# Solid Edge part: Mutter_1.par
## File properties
Sűrűség: 0,000 kg/m^3
Pontosság: 0,990
Author: ahadarics
Last saved by: ahadarics
Revision: 77
Username: ahadarics
Dokumentum tartalom típus: 0
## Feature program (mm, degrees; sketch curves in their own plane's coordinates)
base feature "unnamed BaseFeature 1"
thread "unnamed Thread 1"
chamfer "Letörés_1"  SetBackValue2 = 60 deg
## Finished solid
Body 1: solid body, 23 faces, 46 edges, 24 vertices.
  Faces by surface: cone 14, plane 8, cylinder 1
  Edges by curve: spline 24, circle 16, line 6
Bounding box of the edges (mm): 4.000 x 11.547 x 10.000, from (0, -5.7735, -5) to (4, 5.7735, 5).
Cylindrical faces by radius (mm): R2.4585 x1
Conical faces (half-angle, radius in mm at the cone's reference point): 60 deg R2.4585 x1, 60 deg R2.9781 x1, 60 deg R5.3868 x12
Planar faces by outward normal: +x 1, +z 1, -x 1, -z 1, oblique 4
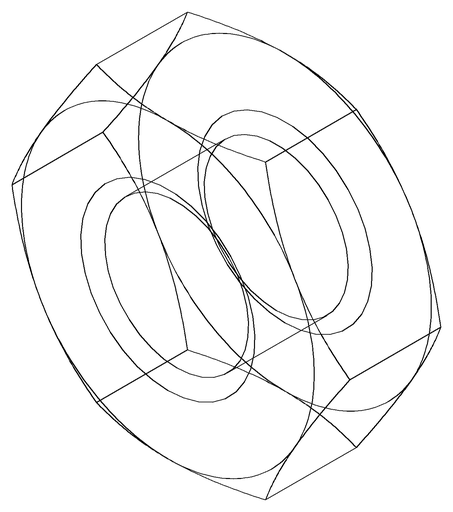
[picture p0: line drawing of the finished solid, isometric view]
